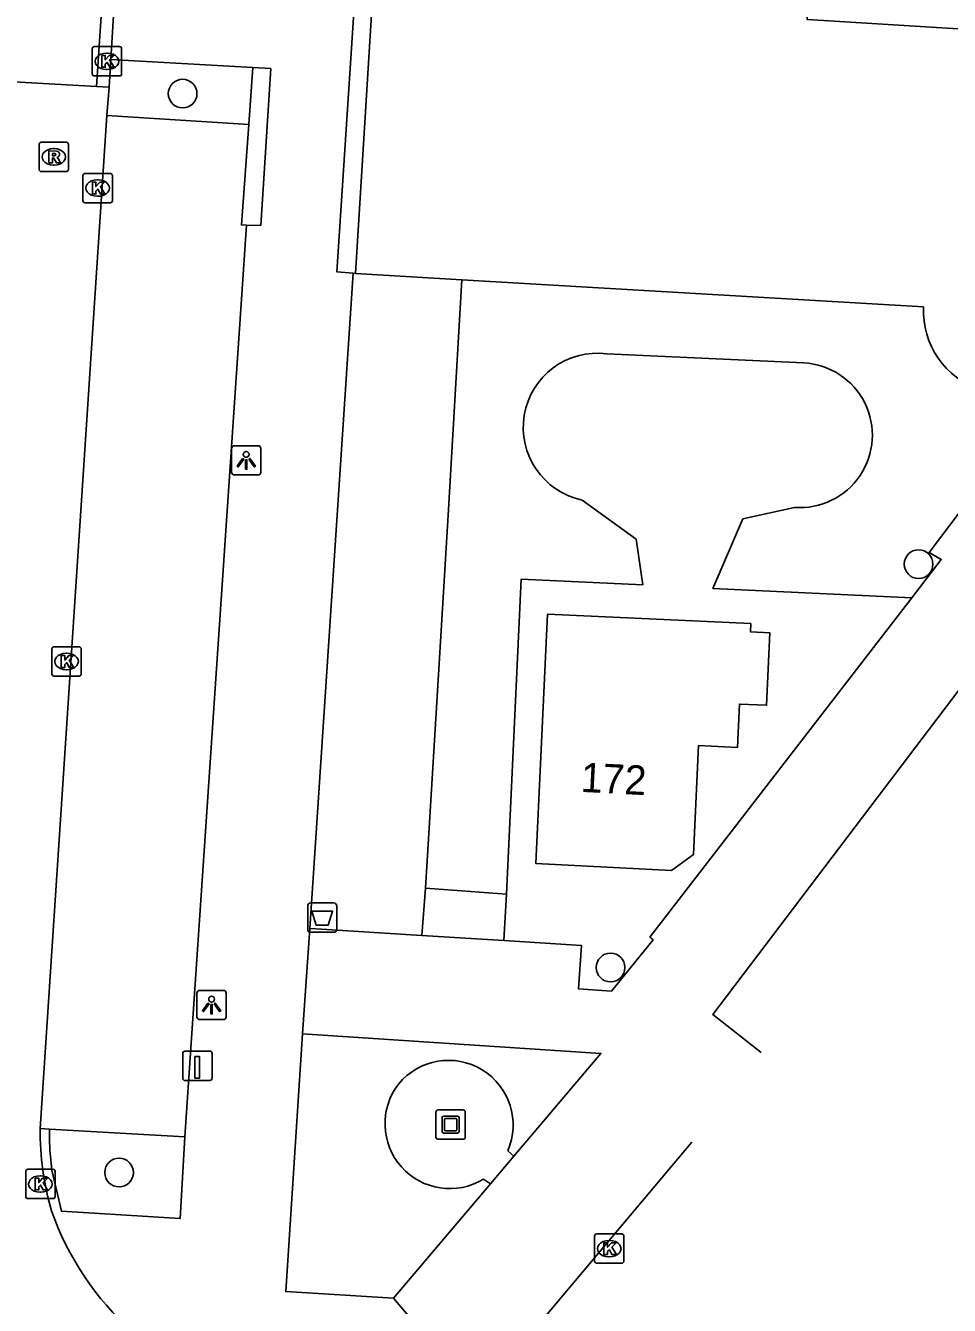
# Model space of a CAD drawing. Extents: x 160107 to 160928, y 382056 to 382918.
# Drawn here: x 160544.87 to 160576.34, y 382297.58 to 382341.17 of the extents above; entities that cross this region are included whole.
import ezdxf

# ---------------------------------------------------------------- set-up
doc = ezdxf.new("R2010")
doc.units = 0
for name, color, linetype in [('IMGEO_Afvalbak', 7, 'Continuous'), ('IMGEO_Boom', 7, 'Continuous'), ('IMGEO_Groenvoorziening', 7, 'Continuous'), ('IMGEO_Haag', 7, 'Continuous'), ('IMGEO_Kolk', 7, 'Continuous'), ('IMGEO_Kunstobject', 7, 'Continuous'), ('IMGEO_Laadpaal', 7, 'Continuous'), ('IMGEO_Lichtpunt', 7, 'Continuous'), ('IMGEO_Pand', 7, 'Continuous'), ('IMGEO_Pand_nummerreeks', 7, 'Continuous'), ('IMGEO_Parkeervlak_open', 7, 'Continuous'), ('IMGEO_Rijbaan_lokaal_open', 7, 'Continuous'), ('IMGEO_Rioolput', 7, 'Continuous'), ('IMGEO_Voetpad_open', 7, 'Continuous')]:
    doc.layers.add(name, color=color, linetype=linetype)

msp = doc.modelspace()

# ---------------------------------------------------------------- linework, layer by layer
at = {"layer": 'IMGEO_Afvalbak'}
for p, q in [((160554.482, 382310.386), (160554.482, 382311.186)), ((160554.482, 382311.186), (160554.482, 382310.386)), ((160554.582, 382311.286), (160555.372, 382311.286)), ((160555.372, 382311.286), (160554.582, 382311.286)), ((160555.472, 382311.186), (160555.472, 382310.386)), ((160555.472, 382310.386), (160555.472, 382311.186)), ((160555.372, 382310.286), (160554.582, 382310.286)), ((160554.582, 382310.286), (160555.372, 382310.286))]:
    msp.add_line(p, q, dxfattribs=at)
msp.add_lwpolyline([(160554.625, 382311), (160555.329, 382311), (160555.18, 382310.53), (160554.774, 382310.53), (160554.625, 382311)], dxfattribs=at)
for centre, start, end in [((160554.582, 382311.186), 90, 180), ((160554.582, 382311.186), 90, 180), ((160555.372, 382311.186), 0, 90), ((160555.372, 382311.186), 360, 90), ((160554.582, 382310.386), 180, 270), ((160554.582, 382310.386), 180, 270), ((160555.372, 382310.386), 270, 0), ((160555.372, 382310.386), 270, 0)]:
    msp.add_arc(centre, 0.1, start, end, dxfattribs=at)
at = {"layer": 'IMGEO_Boom'}
for centre in [(160550.22, 382338.853), (160575.287, 382322.826), (160564.796, 382309.086), (160548.055, 382302.103)]:
    msp.add_circle(centre, 0.489, dxfattribs=at)
at = {"layer": 'IMGEO_Groenvoorziening'}
for points in [[(160558.488, 382311.794), (160558.967, 382319.628), (160559.278, 382324.692), (160559.732, 382332.515)], [(160558.488, 382311.794), (160558.37, 382310.178)], [(160561.253, 382311.585), (160558.488, 382311.794)]]:
    msp.add_lwpolyline(points, dxfattribs=at)
at = {"layer": 'IMGEO_Haag'}
for points in [[(160552.613, 382339.739), (160552.471, 382337.806)], [(160556.108, 382332.729), (160556.032, 382332.735)]]:
    msp.add_lwpolyline(points, dxfattribs=at)
at = {"layer": 'IMGEO_Kolk'}
for p, q in [((160547.142, 382339.527), (160547.142, 382340.379)), ((160547.217, 382340.453), (160548.069, 382340.453)), ((160547.63, 382340.233), (160547.655, 382340.233)), ((160548.143, 382340.379), (160548.143, 382339.527)), ((160547.653, 382339.673), (160547.628, 382339.673)), ((160548.069, 382339.453), (160547.217, 382339.453)), ((160546.825, 382335.209), (160546.825, 382336.061)), ((160546.9, 382336.135), (160547.752, 382336.135)), ((160547.313, 382335.915), (160547.338, 382335.915)), ((160547.826, 382336.061), (160547.826, 382335.209)), ((160547.336, 382335.355), (160547.311, 382335.355)), ((160547.752, 382335.135), (160546.9, 382335.135)), ((160545.767, 382319.084), (160545.767, 382319.936)), ((160545.842, 382320.01), (160546.694, 382320.01)), ((160546.255, 382319.79), (160546.28, 382319.79)), ((160546.768, 382319.936), (160546.768, 382319.084)), ((160546.278, 382319.23), (160546.253, 382319.23)), ((160546.694, 382319.01), (160545.842, 382319.01)), ((160544.949, 382302.213), (160545.801, 382302.213)), ((160544.874, 382301.287), (160544.874, 382302.139)), ((160545.362, 382301.993), (160545.387, 382301.993)), ((160545.875, 382302.139), (160545.875, 382301.287)), ((160545.385, 382301.433), (160545.36, 382301.433)), ((160545.801, 382301.213), (160544.949, 382301.213)), ((160564.325, 382300.011), (160565.177, 382300.011)), ((160564.25, 382299.085), (160564.25, 382299.937)), ((160564.738, 382299.791), (160564.763, 382299.791)), ((160565.251, 382299.937), (160565.251, 382299.085)), ((160564.761, 382299.231), (160564.736, 382299.231)), ((160565.177, 382299.011), (160564.325, 382299.011))]:
    msp.add_line(p, q, dxfattribs=at)
for points in [[(160547.142, 382339.527), (160547.142, 382340.379)], [(160547.217, 382340.453), (160548.069, 382340.453)], [(160547.463, 382340.153), (160547.586, 382340.153), (160547.586, 382340.002), (160547.716, 382340.153), (160547.88, 382340.153), (160547.734, 382340.002), (160547.887, 382339.753), (160547.735, 382339.753), (160547.65, 382339.917), (160547.586, 382339.85), (160547.586, 382339.753), (160547.463, 382339.753), (160547.463, 382340.153)], [(160548.143, 382340.379), (160548.143, 382339.527)], [(160548.069, 382339.453), (160547.217, 382339.453)], [(160546.825, 382335.209), (160546.825, 382336.061)], [(160546.9, 382336.135), (160547.752, 382336.135)], [(160547.146, 382335.835), (160547.269, 382335.835), (160547.269, 382335.684), (160547.399, 382335.835), (160547.563, 382335.835), (160547.417, 382335.684), (160547.57, 382335.435), (160547.418, 382335.435), (160547.333, 382335.599), (160547.269, 382335.532), (160547.269, 382335.435), (160547.146, 382335.435), (160547.146, 382335.835)], [(160547.826, 382336.061), (160547.826, 382335.209)], [(160547.752, 382335.135), (160546.9, 382335.135)], [(160545.767, 382319.084), (160545.767, 382319.936)], [(160545.842, 382320.01), (160546.694, 382320.01)], [(160546.088, 382319.71), (160546.211, 382319.71), (160546.211, 382319.559), (160546.341, 382319.71), (160546.505, 382319.71), (160546.359, 382319.559), (160546.512, 382319.31), (160546.36, 382319.31), (160546.275, 382319.474), (160546.211, 382319.407), (160546.211, 382319.31), (160546.088, 382319.31), (160546.088, 382319.71)], [(160546.768, 382319.936), (160546.768, 382319.084)], [(160546.694, 382319.01), (160545.842, 382319.01)], [(160544.949, 382302.213), (160545.801, 382302.213)], [(160544.874, 382301.287), (160544.874, 382302.139)], [(160545.195, 382301.913), (160545.318, 382301.913), (160545.318, 382301.762), (160545.448, 382301.913), (160545.612, 382301.913), (160545.466, 382301.762), (160545.619, 382301.513), (160545.467, 382301.513), (160545.382, 382301.677), (160545.318, 382301.61), (160545.318, 382301.513), (160545.195, 382301.513), (160545.195, 382301.913)], [(160545.875, 382302.139), (160545.875, 382301.287)], [(160545.801, 382301.213), (160544.949, 382301.213)], [(160564.325, 382300.011), (160565.177, 382300.011)], [(160564.25, 382299.085), (160564.25, 382299.937)], [(160564.571, 382299.711), (160564.694, 382299.711), (160564.694, 382299.56), (160564.824, 382299.711), (160564.988, 382299.711), (160564.842, 382299.56), (160564.995, 382299.311), (160564.843, 382299.311), (160564.758, 382299.475), (160564.694, 382299.408), (160564.694, 382299.311), (160564.571, 382299.311), (160564.571, 382299.711)], [(160565.251, 382299.937), (160565.251, 382299.085)], [(160565.177, 382299.011), (160564.325, 382299.011)]]:
    msp.add_lwpolyline(points, dxfattribs=at)
for centre, start, end in [((160547.219, 382340.377), 91.552, 178.448), ((160547.219, 382340.377), 91.552, 178.448), ((160548.067, 382340.377), 1.552, 88.448), ((160548.067, 382340.377), 1.552, 88.448), ((160547.219, 382339.529), 181.552, 268.448), ((160547.219, 382339.529), 181.552, 268.448), ((160548.067, 382339.529), 271.552, 358.448), ((160548.067, 382339.529), 271.552, 358.448), ((160546.902, 382336.059), 91.552, 178.448), ((160546.902, 382336.059), 91.552, 178.448), ((160547.75, 382336.059), 1.552, 88.448), ((160547.75, 382336.059), 1.552, 88.448), ((160546.902, 382335.211), 181.552, 268.448), ((160546.902, 382335.211), 181.552, 268.448), ((160547.75, 382335.211), 271.552, 358.448), ((160547.75, 382335.211), 271.552, 358.448), ((160545.844, 382319.934), 91.552, 178.448), ((160545.844, 382319.934), 91.552, 178.448), ((160546.692, 382319.934), 1.552, 88.448), ((160546.692, 382319.934), 1.552, 88.448), ((160545.844, 382319.086), 181.552, 268.448), ((160545.844, 382319.086), 181.552, 268.448), ((160546.692, 382319.086), 271.552, 358.448), ((160546.692, 382319.086), 271.552, 358.448), ((160544.951, 382302.137), 91.552, 178.448), ((160544.951, 382302.137), 91.552, 178.448), ((160545.799, 382302.137), 1.552, 88.448), ((160545.799, 382302.137), 1.552, 88.448), ((160544.951, 382301.289), 181.552, 268.448), ((160544.951, 382301.289), 181.552, 268.448), ((160545.799, 382301.289), 271.552, 358.448), ((160545.799, 382301.289), 271.552, 358.448), ((160564.327, 382299.935), 91.552, 178.448), ((160564.327, 382299.935), 91.552, 178.448), ((160565.175, 382299.935), 1.552, 88.448), ((160565.175, 382299.935), 1.552, 88.448), ((160564.327, 382299.087), 181.552, 268.448), ((160564.327, 382299.087), 181.552, 268.448), ((160565.175, 382299.087), 271.552, 358.448), ((160565.175, 382299.087), 271.552, 358.448)]:
    msp.add_arc(centre, 0.0765, start, end, dxfattribs=at)
for centre, major_axis, ratio, start_param, end_param in [((160547.629, 382339.953), (-0.387, 0.002), 0.722429, 4.712389, 7.853982), ((160547.654, 382339.953), (-0.39, 0.002), 0.717154, 1.570796, 4.712389), ((160547.312, 382335.635), (-0.387, 0.002), 0.722429, 4.712389, 7.853982), ((160547.337, 382335.635), (-0.39, 0.002), 0.717154, 1.570796, 4.712389), ((160546.254, 382319.51), (-0.387, 0.002), 0.722429, 4.712389, 7.853982), ((160546.279, 382319.51), (-0.39, 0.002), 0.717154, 1.570796, 4.712389), ((160545.361, 382301.713), (-0.387, 0.002), 0.722429, 4.712389, 7.853982), ((160545.386, 382301.713), (-0.39, 0.002), 0.717154, 1.570796, 4.712389), ((160564.737, 382299.511), (-0.387, 0.002), 0.722429, 4.712389, 7.853982), ((160564.762, 382299.511), (-0.39, 0.002), 0.717154, 1.570796, 4.712389)]:
    msp.add_ellipse(centre, major_axis=major_axis, ratio=ratio, start_param=start_param, end_param=end_param, dxfattribs=at)
at = {"layer": 'IMGEO_Kunstobject'}
for p, q in [((160558.848, 382304.15), (160558.848, 382303.309)), ((160558.848, 382304.15), (160558.848, 382303.309)), ((160559.764, 382304.234), (160558.923, 382304.234)), ((160559.764, 382304.234), (160558.923, 382304.234)), ((160559.062, 382303.498), (160559.062, 382303.972)), ((160559.112, 382304.022), (160559.586, 382304.022)), ((160559.536, 382303.942), (160559.162, 382303.942)), ((160559.636, 382303.972), (160559.636, 382303.498)), ((160559.848, 382303.318), (160559.848, 382304.159)), ((160559.848, 382303.318), (160559.848, 382304.159)), ((160559.142, 382303.922), (160559.142, 382303.548)), ((160559.162, 382303.528), (160559.536, 382303.528)), ((160559.556, 382303.548), (160559.556, 382303.922)), ((160558.932, 382303.234), (160559.773, 382303.234)), ((160558.932, 382303.234), (160559.773, 382303.234)), ((160559.586, 382303.448), (160559.112, 382303.448))]:
    msp.add_line(p, q, dxfattribs=at)
for centre, radius, start, end in [((160558.926, 382304.156), 0.0779, 92.4484, 184.2845), ((160558.926, 382304.156), 0.0779, 92.4484, 184.2845), ((160559.112, 382303.972), 0.05, 90, 180), ((160559.162, 382303.922), 0.02, 90, 180), ((160559.536, 382303.922), 0.02, 360, 90), ((160559.586, 382303.972), 0.05, 360, 90), ((160559.77, 382304.156), 0.0779, 2.4484, 94.2845), ((160559.77, 382304.156), 0.0779, 2.4484, 94.2845), ((160559.112, 382303.498), 0.05, 180, 270), ((160559.162, 382303.548), 0.02, 180, 270), ((160559.536, 382303.548), 0.02, 270, 0), ((160559.586, 382303.498), 0.05, 270, 0), ((160558.926, 382303.312), 0.0779, 182.4484, 274.2845), ((160558.926, 382303.312), 0.0779, 182.4484, 274.2845), ((160559.77, 382303.312), 0.0779, 272.4484, 4.2845), ((160559.77, 382303.312), 0.0779, 272.4484, 4.2845)]:
    msp.add_arc(centre, radius, start, end, dxfattribs=at)
at = {"layer": 'IMGEO_Laadpaal'}
for p, q in [((160550.224, 382306.153), (160550.224, 382305.312)), ((160550.224, 382306.153), (160550.224, 382305.312)), ((160551.14, 382306.237), (160550.299, 382306.237)), ((160551.14, 382306.237), (160550.299, 382306.237)), ((160551.224, 382305.321), (160551.224, 382306.162)), ((160551.224, 382305.321), (160551.224, 382306.162)), ((160550.308, 382305.237), (160551.149, 382305.237)), ((160550.308, 382305.237), (160551.149, 382305.237))]:
    msp.add_line(p, q, dxfattribs=at)
msp.add_lwpolyline([(160550.639, 382306.05), (160550.799, 382306.05), (160550.799, 382305.317), (160550.639, 382305.317), (160550.639, 382306.05)], dxfattribs=at)
for centre, start, end in [((160550.302, 382306.159), 92.4484, 184.2845), ((160550.302, 382306.159), 92.4484, 184.2845), ((160551.146, 382306.159), 2.4484, 94.2845), ((160551.146, 382306.159), 2.4484, 94.2845), ((160550.302, 382305.315), 182.4484, 274.2845), ((160550.302, 382305.315), 182.4484, 274.2845), ((160551.146, 382305.315), 272.4484, 4.2845), ((160551.146, 382305.315), 272.4484, 4.2845)]:
    msp.add_arc(centre, 0.0779, start, end, dxfattribs=at)
at = {"layer": 'IMGEO_Lichtpunt'}
for p, q in [((160551.887, 382326.765), (160551.887, 382325.958)), ((160551.887, 382326.765), (160551.887, 382325.958)), ((160552.789, 382326.86), (160551.981, 382326.86)), ((160552.789, 382326.86), (160551.981, 382326.86)), ((160552.883, 382325.958), (160552.883, 382326.765)), ((160552.883, 382325.958), (160552.883, 382326.765)), ((160551.981, 382325.864), (160552.789, 382325.864)), ((160551.981, 382325.864), (160552.789, 382325.864)), ((160551.61, 382308.307), (160550.802, 382308.307)), ((160551.61, 382308.307), (160550.802, 382308.307)), ((160550.708, 382308.212), (160550.708, 382307.405)), ((160550.708, 382308.212), (160550.708, 382307.405)), ((160551.704, 382307.405), (160551.704, 382308.212)), ((160551.704, 382307.405), (160551.704, 382308.212)), ((160550.802, 382307.311), (160551.61, 382307.311)), ((160550.802, 382307.311), (160551.61, 382307.311))]:
    msp.add_line(p, q, dxfattribs=at)
for points in [[(160552.261, 382326.429), (160552.3, 382326.401), (160552.112, 382326.139), (160552.074, 382326.166), (160552.261, 382326.429)], [(160552.363, 382326.381), (160552.41, 382326.381), (160552.41, 382326.059), (160552.363, 382326.059), (160552.363, 382326.381)], [(160552.473, 382326.401), (160552.511, 382326.428), (160552.698, 382326.166), (160552.659, 382326.138), (160552.473, 382326.401)], [(160551.082, 382307.876), (160551.121, 382307.848), (160550.933, 382307.586), (160550.895, 382307.613), (160551.082, 382307.876)], [(160551.294, 382307.848), (160551.332, 382307.875), (160551.519, 382307.613), (160551.48, 382307.585), (160551.294, 382307.848)], [(160551.184, 382307.828), (160551.231, 382307.828), (160551.231, 382307.506), (160551.184, 382307.506), (160551.184, 382307.828)]]:
    msp.add_lwpolyline(points, dxfattribs=at)
for centre in [(160552.386, 382326.563), (160551.207, 382308.01)]:
    msp.add_circle(centre, 0.0994, dxfattribs=at)
for centre, start, end in [((160551.981, 382326.765), 90, 180), ((160551.981, 382326.765), 90, 180), ((160552.789, 382326.765), 0, 90), ((160552.789, 382326.765), 0, 90), ((160551.981, 382325.958), 180, 270), ((160551.981, 382325.958), 180, 270), ((160552.789, 382325.958), 270, 0), ((160552.789, 382325.958), 270, 360), ((160550.802, 382308.212), 90, 180), ((160550.802, 382308.212), 90, 180), ((160551.61, 382308.212), 0, 90), ((160551.61, 382308.212), 0, 90), ((160550.802, 382307.405), 180, 270), ((160550.802, 382307.405), 180, 270), ((160551.61, 382307.405), 270, 0), ((160551.61, 382307.405), 270, 360)]:
    msp.add_arc(centre, 0.0946, start, end, dxfattribs=at)
at = {"layer": 'IMGEO_Pand'}
for points in [[(160587.757, 382339.068), (160585.979, 382340.453), (160586.26, 382345.268), (160586.342, 382346.677), (160591.48, 382346.353), (160593.688, 382349.22), (160585.586, 382355.449), (160583.507, 382357.047), (160581.575, 382357.12), (160580.676, 382340.81), (160571.49, 382341.378), (160571.897, 382347.942), (160569.6, 382348.084), (160569.194, 382341.52), (160556.703, 382342.293)], [(160556.108, 382332.729), (160556.703, 382342.293)], [(160559.732, 382332.515), (160556.108, 382332.729)], [(160575.46, 382331.588), (160559.732, 382332.515)], [(160569.578, 382320.801), (160569.564, 382320.516), (160570.225, 382320.485), (160570.11, 382318.017), (160569.186, 382318.06), (160569.118, 382316.582), (160567.791, 382316.644), (160567.618, 382312.932), (160566.874, 382312.387), (160562.252, 382312.625), (160562.648, 382321.124), (160569.578, 382320.801)]]:
    msp.add_lwpolyline(points, dxfattribs=at)
msp.add_arc((160578.256, 382331.432), 2.8, 176.8105, 252.5207, dxfattribs=at)
at = {"layer": 'IMGEO_Parkeervlak_open'}
for points in [[(160547.716, 382339.069), (160547.775, 382340.016)], [(160552.471, 382337.806), (160547.643, 382338.109)], [(160552.39, 382334.377), (160552.22, 382334.382), (160552.471, 382337.806)], [(160571.383, 382329.68), (160564.67, 382329.991)], [(160563.833, 382325.007), (160565.673, 382323.675), (160565.891, 382322.122), (160561.752, 382322.315), (160561.253, 382311.585)], [(160575.055, 382321.682), (160568.281, 382321.998), (160569.303, 382324.364), (160571.065, 382324.756)], [(160561.163, 382310.005), (160561.253, 382311.585)], [(160550.299, 382303.313), (160545.688, 382303.581)]]:
    msp.add_lwpolyline(points, dxfattribs=at)
for centre, radius, start, end in [((160564.351, 382327.482), 2.529, 82.7535, 258.1802), ((160571.245, 382327.217), 2.467, 265.8188, 86.791)]:
    msp.add_arc(centre, radius, start, end, dxfattribs=at)
at = {"layer": 'IMGEO_Rijbaan_lokaal_open'}
for points in [[(160547.289, 382339.093), (160551.035, 382395.683)], [(160541.437, 382339.428), (160547.289, 382339.093)], [(160547.716, 382339.069), (160547.289, 382339.093)], [(160547.643, 382338.109), (160547.716, 382339.069)], [(160545.367, 382303.6), (160547.643, 382338.109)], [(160560.3, 382294.499), (160567.566, 382303.142)]]:
    msp.add_lwpolyline(points, dxfattribs=at)
for centre, radius, start, end in [((160554.768, 382303.474), 9.401, 179.2313, 196.5362), ((160555.175, 382304.113), 9.986, 199.3852, 256.4601)]:
    msp.add_arc(centre, radius, start, end, dxfattribs=at)
at = {"layer": 'IMGEO_Rioolput'}
for p, q in [((160545.33, 382336.272), (160545.33, 382337.124)), ((160545.405, 382337.198), (160546.257, 382337.198)), ((160546.331, 382337.124), (160546.331, 382336.272)), ((160545.818, 382336.978), (160545.843, 382336.978)), ((160546.257, 382336.198), (160545.405, 382336.198)), ((160545.841, 382336.418), (160545.816, 382336.418))]:
    msp.add_line(p, q, dxfattribs=at)
for points in [[(160545.33, 382336.272), (160545.33, 382337.124)], [(160545.405, 382337.198), (160546.257, 382337.198)], [(160546.331, 382337.124), (160546.331, 382336.272)], [(160545.919, 382336.896), (160545.667, 382336.898), (160545.667, 382336.498)], [(160545.667, 382336.498), (160545.791, 382336.498), (160545.791, 382336.66), (160545.802, 382336.66)], [(160545.845, 382336.817), (160545.791, 382336.817), (160545.791, 382336.736)], [(160545.791, 382336.736), (160545.843, 382336.736)], [(160545.849, 382336.631), (160545.92, 382336.498), (160546.06, 382336.498), (160545.995, 382336.624)], [(160546.257, 382336.198), (160545.405, 382336.198)]]:
    msp.add_lwpolyline(points, dxfattribs=at)
for centre, radius, start, end in [((160545.407, 382337.122), 0.0765, 91.552, 178.448), ((160545.407, 382337.122), 0.0765, 91.552, 178.448), ((160546.255, 382337.122), 0.0765, 1.552, 88.448), ((160546.255, 382337.122), 0.0765, 1.552, 88.448), ((160545.801, 382336.607), 0.0533, 26.0293, 88.6989), ((160545.827, 382336.925), 0.19, 274.7715, 282.9687), ((160545.851, 382336.721), 0.0964, 77.0061, 93.1865), ((160545.865, 382336.778), 0.0378, 276.6634, 79.6772), ((160545.918, 382336.786), 0.109, 350.3612, 89.416), ((160545.916, 382336.786), 0.112, 277.5842, 350.9817), ((160545.9, 382336.571), 0.108, 29.5134, 73.7905), ((160545.407, 382336.274), 0.0765, 181.552, 268.448), ((160545.407, 382336.274), 0.0765, 181.552, 268.448), ((160546.255, 382336.274), 0.0765, 271.552, 358.448), ((160546.255, 382336.274), 0.0765, 271.552, 358.448)]:
    msp.add_arc(centre, radius, start, end, dxfattribs=at)
for centre, major_axis, ratio, start_param, end_param in [((160545.817, 382336.698), (-0.387, 0.002), 0.722429, 4.712389, 7.853982), ((160545.842, 382336.698), (-0.39, 0.002), 0.717154, 1.570796, 4.712389)]:
    msp.add_ellipse(centre, major_axis=major_axis, ratio=ratio, start_param=start_param, end_param=end_param, dxfattribs=at)
at = {"layer": 'IMGEO_Voetpad_open'}
for points in [[(160556.703, 382342.293), (160556.093, 382342.324), (160555.474, 382332.78), (160556.032, 382332.735)], [(160547.775, 382340.016), (160547.892, 382341.885)], [(160552.613, 382339.739), (160547.775, 382340.016)], [(160552.39, 382334.377), (160552.888, 382334.361), (160553.224, 382339.704), (160552.613, 382339.739)], [(160550.299, 382303.313), (160552.39, 382334.377)], [(160556.032, 382332.735), (160554.554, 382310.417)], [(160580.462, 382329.597), (160575.644, 382323.217), (160576.061, 382322.986), (160575.055, 382321.682)], [(160569.92, 382306.193), (160568.279, 382307.486), (160583.534, 382327.606), (160585.312, 382326.246)], [(160575.055, 382321.682), (160566.139, 382310.125), (160566.249, 382310.026), (160564.822, 382308.277), (160563.703, 382308.36), (160563.805, 382309.841), (160561.163, 382310.005)], [(160554.554, 382310.417), (160554.302, 382306.831)], [(160558.37, 382310.178), (160554.947, 382310.391), (160554.554, 382310.417)], [(160561.163, 382310.005), (160558.37, 382310.178)], [(160554.302, 382306.831), (160553.732, 382298.045), (160557.4, 382297.821)], [(160554.302, 382306.831), (160564.469, 382306.158), (160561.499, 382302.656)], [(160545.367, 382303.6), (160545.688, 382303.581)], [(160545.688, 382303.581), (160545.685, 382303.406), (160545.685, 382303.23), (160545.697, 382302.878), (160545.766, 382302.179), (160546.091, 382300.784), (160550.132, 382300.533), (160550.299, 382303.313)], [(160561.499, 382302.656), (160560.705, 382301.719)], [(160561.294, 382302.846), (160561.499, 382302.656)], [(160560.705, 382301.719), (160560.468, 382301.877)], [(160560.705, 382301.719), (160557.4, 382297.821)], [(160557.4, 382297.821), (160559.96, 382294.804)]]:
    msp.add_lwpolyline(points, dxfattribs=at)
for centre, radius, start, end in [((160559.275, 382303.722), 2.201, 336.5341, 140.6367), ((160559.321, 382303.765), 2.209, 142.2436, 301.282)]:
    msp.add_arc(centre, radius, start, end, dxfattribs=at)

# ---------------------------------------------------------------- texts
at = {"layer": 'IMGEO_Pand_nummerreeks'}
msp.add_text('172', height=1, rotation=357.0523, dxfattribs=at).set_placement((160563.763, 382315.07))

doc.saveas('drawing.dxf')
